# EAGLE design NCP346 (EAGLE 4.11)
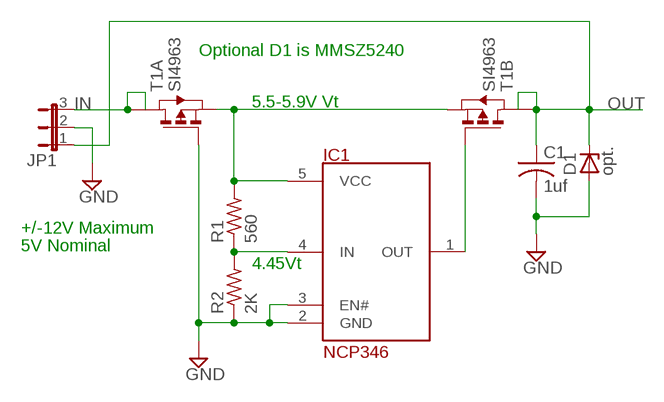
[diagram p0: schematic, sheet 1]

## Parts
C1  1uf  C-USC1206  [C1206]
D1  opt.  ZENER-DIODESOD80C  [SOD80C]
IC1  NCP346  [SOT23-5]
JP1  JP2W  [JP2W]
R1  560  R-US_R0603  [R0603]
R2  2K  R-US_R0603  [R0603]
T1  SI4963  [SO8]

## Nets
GND [power]: C1.2 D1.A IC1.2(GND) IC1.3(EN#) JP1.2 R2.1 T1.4(A:G)
IN [power]: JP1.3 T1.5(A:D) T1.6(A:D1)
N$2: IC1.1(OUT) T1.2(B:G)
N$3: IC1.4(IN) R1.1 R2.2
OUT [power]: C1.1 D1.C JP1.1 T1.7(B:D) T1.8(B:D1)
VCC [power]: IC1.5(VCC) R1.2 T1.1(B:S) T1.3(A:S)

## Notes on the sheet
- Optional D1 is MMSZ5240
- 5.5-5.9V Vt
- +/-12V Maximum
- 5V Nominal
- 4.45Vt

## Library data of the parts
C1 = rcl:C-US: CAPACITOR, American symbol
D1 = diode:ZENER-DIODE: Z-Diode
IC1 = OverVoltage:NCP346: NCP346 Voltage Protection
JP1 = jumper:JP2W: JUMPER
R1 R2 = rcl:R-US_: RESISTOR, American symbol
T1 = OverVoltage:SI4963: Dual P-MOSFET 20V 6.2A

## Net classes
1 power: width 0.762 mm

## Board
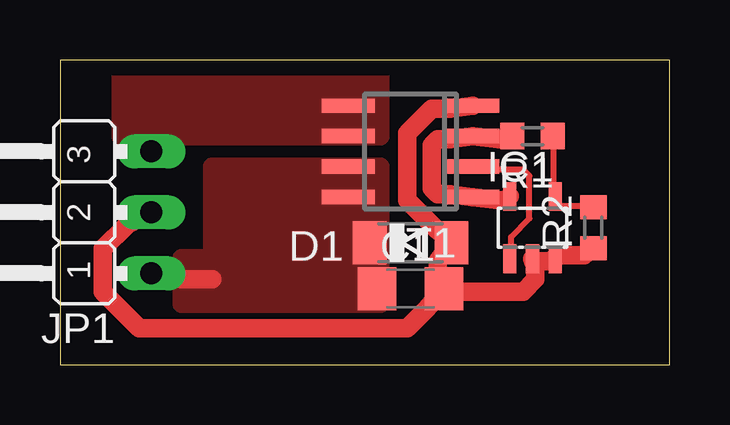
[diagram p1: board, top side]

Size 25.4 x 12.7 mm. Coordinates in mm from the lower left corner, seen from the top.
Outline: 0,0 25.4,0 25.4,12.7 0,12.7 0,0
Copper layers (1*16): Top 0.035mm / dielectric 1.5mm / Bottom 0.035mm
Design rules "default": minimum track width 10mil, minimum drill 24mil, track to track 8mil, track to pad 8mil, pad to pad 8mil, via to via 8mil, smd to smd 0mil, copper to edge 25mil, drill to drill 8mil, minimum pad ring 10mil, minimum via ring 8mil, stop-mask expansion 4mil, vias tented up to drill 0mil, thermal gap 10mil

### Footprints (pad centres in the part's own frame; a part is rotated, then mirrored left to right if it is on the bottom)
C1206 = smd 1.6 x 1.8: 1 -1.4,0; 2 1.4,0
SOD80C = smd 1.4 x 1.8: A 1.7,0; C -1.7,0
SOT23-5 = smd 0.55 x 1.2: 1 -0.95,-1.3; 2 0,-1.3; 3 0.95,-1.3; 4 0.95,1.3; 5 -0.95,1.3
JP2W = drill 0.914 long: 1 -2.54,-1.27; 2 0,-1.27; 3 2.54,-1.27
R0603 = smd 1 x 1.1: 1 -0.85,0; 2 0.85,0
SO8 = smd 0.6 x 2.2: 1 -1.905,-2.6; 2 -0.635,-2.6; 3 0.635,-2.6; 4 1.905,-2.6; 5 1.905,2.6; 6 0.635,2.6; 7 -0.635,2.6; 8 -1.905,2.6

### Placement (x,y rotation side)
C1  14.61,3.17 0 top
D1  14.61,5.08 0 top
IC1  19.68,5.71 0 top
JP1  2.54,6.35 90 top
R1  19.68,9.53 180 top
R2  22.23,5.71 90 top
T1  14.61,8.89 90 top

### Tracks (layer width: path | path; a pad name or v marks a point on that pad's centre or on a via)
GND
  Top 0.762: R2.1 21.84,4.57 20.83,4.57 IC1.3 20.32,4.32 19.81,4.32 IC1.2 19.81,4.06 19.81,3.56 19.3,3.05 16.76,3.05 C1.2 | C1.2 15.75,4.06 15.75,4.32 D1.A 15.75,5.59 14.48,6.86 14.48,9.65 15.49,10.67 16.26,10.67 T1.4 | JP1.2 2.79,5.84 1.78,4.83 1.78,3.05 3.3,1.52 14.48,1.52 15.24,2.29 C1.2
IN
  pour Top (no thermals): 2.54,9.53 13.34,9.53 13.34,12.7 2.54,12.7
N$2
  Top 0.254: IC1.1 18.8,4.83 18.8,5.33 19.56,6.1 19.56,7.87 19.3,8.13 18.29,8.13 T1.2
N$3
  Top 0.254: R2.2 21.84,6.6 20.83,6.6 IC1.4 20.57,7.37 20.57,9.14 R1.1
OUT
  Top 0.762: JP1.1 5.08,3.56 6.1,3.56 6.35,3.56
  pour Top (no thermals): 6.35,2.54 6.35,8.26 13.34,8.26 13.34,2.54
  pour Top (no thermals): 6.35,2.54 5.08,2.54 5.08,4.45 6.35,4.45
VCC
  Top 0.762: IC1.5 18.54,6.86 18.29,6.86 T1.1 16.26,7.11 15.75,7.11 15.49,7.37 15.49,9.14 15.75,9.4 16.26,9.4 T1.3 18.29,9.4 18.54,9.4 R1.2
